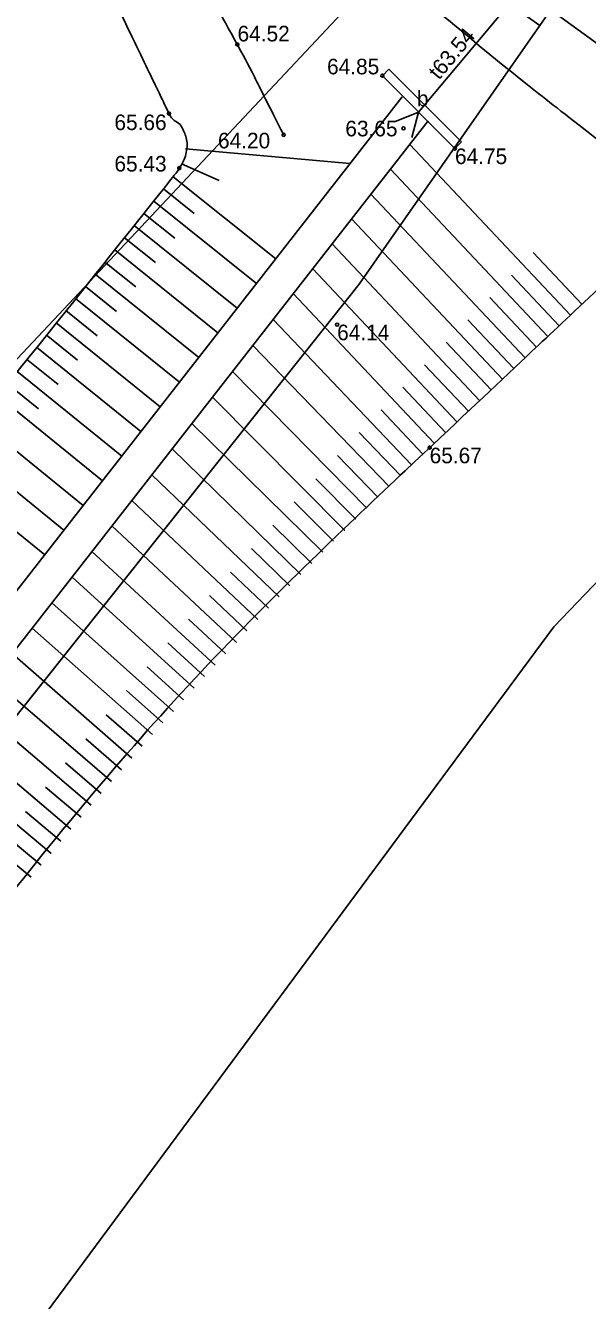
# Model space of a CAD drawing. Extents: x 616607 to 617499, y 408385 to 409695.
# Drawn here: x 617315.69 to 617333.71, y 409488.71 to 409529.59 of the extents above; entities that cross this region are included whole.
import ezdxf

# ---------------------------------------------------------------- set-up
doc = ezdxf.new("R2010")
doc.units = 0
for name, color, linetype in [('BUVE_BDET_####_####_#', 7, 'Continuous'), ('BUVE_BDET_####_TKST_#', 7, 'Continuous'), ('CELI_CMAL_####_####_#', 7, 'Continuous'), ('HIDG_GRAV_####_####_#', 7, 'Continuous'), ('HIDT_CAUR_####_####_#', 7, 'Continuous'), ('HIDT_CAUR_####_TKST_#', 7, 'Continuous'), ('HIDT_ELEM_####_####_#', 7, 'Continuous'), ('RAMI_UZMR_####_####_#', 7, 'Continuous'), ('RELJ_AATZ_####_TKST_#', 7, 'Continuous'), ('RELJ_ELEM_####_####_#', 7, 'Continuous'), ('RELJ_NOGA_####_####_#', 7, 'Continuous'), ('RELJ_NOGL_####_####_#', 7, 'Continuous'), ('ROBZ_PROJ_####_####_#', 7, 'Continuous'), ('ROBZ_UZMR_####_####_#', 7, 'Continuous')]:
    doc.layers.add(name, color=color, linetype=linetype)

# ---------------------------------------------------------------- blocks, each defined once
blk = doc.blocks.new('PKT')
at = {"layer": 'RELJ_ELEM_####_####_#'}
blk.add_circle((0, 0), 0.05, dxfattribs=at)
blk = doc.blocks.new('CAURT')
at = {"layer": 'HIDT_ELEM_####_####_#'}
blk.add_lwpolyline([(0.75, -0.374), (0, 0), (0.75, 0.376)], dxfattribs=at)

msp = doc.modelspace()

# ---------------------------------------------------------------- linework, layer by layer
at = {"layer": 'BUVE_BDET_####_####_#'}
for p, q in [((617327.134, 409527.979), (617327.346, 409528.191)), ((617327.346, 409528.191), (617329.675, 409525.858)), ((617329.463, 409525.646), (617329.675, 409525.858))]:
    msp.add_line(p, q, dxfattribs=at)
msp.add_lwpolyline([(617327.134, 409527.979), (617329.463, 409525.646)], dxfattribs=at)
at = {"layer": 'CELI_CMAL_####_####_#'}
msp.add_lwpolyline([(617323.58, 409536.589), (617338.621, 409525.673)], dxfattribs=at)
at = {"layer": 'HIDG_GRAV_####_####_#'}
for points in [[(617196.049, 409072.553), (617193.886, 409072.979), (617195.921, 409087.874), (617195.921, 409087.874), (617199.518, 409112.516), (617194.569, 409134.842), (617162.019, 409207.474), (617151.93, 409229.107), (617149.428, 409241.28), (617152.359, 409253.938), (617188.564, 409303.055), (617197.968, 409312.659), (617223.456, 409346.169), (617232.567, 409363.51), (617247.671, 409422.509), (617276.576, 409461.456), (617285.007, 409472.526), (617327.765, 409527.3)], [(617198.671, 409072.074), (617200.929, 409072.435), (617202.532, 409075.622), (617201.237, 409087.874), (617202.422, 409112.516), (617197.415, 409136.544), (617162.613, 409207.758), (617153.021, 409229.447), (617150.525, 409241.262), (617153.298, 409253.658), (617189.431, 409302.264), (617198.754, 409312.12), (617224.478, 409345.652), (617234.105, 409363.027), (617250.009, 409421.44), (617285.914, 409471.848), (617328.6, 409526.531)]]:
    msp.add_lwpolyline(points, dxfattribs=at)
at = {"layer": 'HIDT_CAUR_####_####_#'}
msp.add_lwpolyline([(617328.298, 409526.812), (617339.023, 409539.598)], dxfattribs=at)
at = {"layer": 'RAMI_UZMR_####_####_#'}
msp.add_lwpolyline([(617101.571, 408748.246), (617213.472, 409074.039), (617215.883, 409140.56), (617165.121, 409241.478), (617252.137, 409353.424), (617269.572, 409425.099), (617332.631, 409510.312), (617439.945, 409622.037), (617425.373, 409635.959), (617242.079, 409440.82), (617216.614, 409355.716), (617136.613, 409246.751), (617191.828, 409115.62), (617145.545, 408952.8)], dxfattribs=at)
at = {"layer": 'RELJ_NOGA_####_####_#'}
for p, q in [((617319.127, 409529.185), (617319.128, 409529.186)), ((617319.127, 409529.185), (617319.127, 409529.185)), ((617319.344, 409528.735), (617319.344, 409528.735)), ((617319.344, 409528.735), (617319.345, 409528.735)), ((617319.561, 409528.284), (617319.56, 409528.284)), ((617319.561, 409528.284), (617319.562, 409528.285)), ((617319.778, 409527.834), (617319.778, 409527.834)), ((617319.778, 409527.834), (617319.779, 409527.834)), ((617319.995, 409527.383), (617319.994, 409527.383)), ((617319.995, 409527.383), (617319.996, 409527.384)), ((617320.212, 409526.933), (617320.212, 409526.933)), ((617320.212, 409526.933), (617320.213, 409526.933)), ((617320.497, 409526.53), (617320.496, 409526.529)), ((617320.497, 409526.53), (617320.498, 409526.53)), ((617320.783, 409526.132), (617320.783, 409526.132)), ((617320.783, 409526.132), (617320.784, 409526.132)), ((617320.824, 409525.636), (617320.823, 409525.637)), ((617320.824, 409525.636), (617326.095, 409525.161)), ((617333.166, 409520.307), (617328.013, 409525.778)), ((617320.698, 409525.155), (617320.698, 409525.155)), ((617320.698, 409525.155), (617321.901, 409524.624)), ((617320.425, 409524.737), (617320.425, 409524.738)), ((617320.425, 409524.737), (617323.714, 409522.111)), ((617332.438, 409519.621), (617327.39, 409524.981)), ((617320.113, 409524.347), (617320.113, 409524.347)), ((617320.113, 409524.347), (617321.101, 409523.558)), ((617319.801, 409523.956), (617319.8, 409523.957)), ((617319.801, 409523.956), (617323.096, 409521.319)), ((617331.71, 409518.936), (617326.768, 409524.183)), ((617319.489, 409523.566), (617319.489, 409523.566)), ((617319.489, 409523.566), (617320.479, 409522.774)), ((617319.176, 409523.175), (617319.176, 409523.176)), ((617319.176, 409523.175), (617322.481, 409520.531)), ((617330.982, 409518.25), (617326.145, 409523.386)), ((617318.864, 409522.785), (617318.863, 409522.786)), ((617318.864, 409522.785), (617319.856, 409521.99)), ((617318.551, 409522.395), (617318.55, 409522.396)), ((617318.551, 409522.395), (617321.861, 409519.738)), ((617330.254, 409517.564), (617325.523, 409522.588)), ((617333.53, 409520.65), (617331.968, 409522.308)), ((617318.238, 409522.005), (617318.238, 409522.006)), ((617318.238, 409522.005), (617319.233, 409521.207)), ((617317.925, 409521.616), (617317.924, 409521.616)), ((617317.925, 409521.616), (617321.244, 409518.946)), ((617329.527, 409516.879), (617324.9, 409521.791)), ((617332.802, 409519.964), (617331.272, 409521.589)), ((617317.611, 409521.226), (617317.611, 409521.226)), ((617317.611, 409521.226), (617318.609, 409520.424)), ((617317.298, 409520.836), (617317.297, 409520.837)), ((617317.298, 409520.836), (617320.626, 409518.155)), ((617328.799, 409516.193), (617324.277, 409520.993)), ((617332.074, 409519.278), (617330.576, 409520.869)), ((617333.53, 409520.65), (617333.53, 409520.649)), ((617316.984, 409520.447), (617316.984, 409520.447)), ((617316.984, 409520.447), (617317.984, 409519.641)), ((617333.166, 409520.307), (617333.167, 409520.306)), ((617316.67, 409520.058), (617316.67, 409520.058)), ((617316.67, 409520.058), (617320.009, 409517.365)), ((617328.072, 409515.505), (617323.629, 409520.162)), ((617331.346, 409518.593), (617329.879, 409520.15)), ((617332.802, 409519.964), (617332.802, 409519.964)), ((617316.356, 409519.669), (617316.356, 409519.669)), ((617316.356, 409519.669), (617317.359, 409518.859)), ((617330.618, 409517.907), (617329.183, 409519.431)), ((617332.438, 409519.621), (617332.439, 409519.62)), ((617316.042, 409519.28), (617316.041, 409519.28)), ((617316.042, 409519.28), (617319.392, 409516.574)), ((617327.352, 409514.812), (617322.976, 409519.326)), ((617332.074, 409519.278), (617332.075, 409519.278)), ((617315.728, 409518.891), (617315.728, 409518.891)), ((617315.728, 409518.891), (617316.734, 409518.077)), ((617329.891, 409517.221), (617328.487, 409518.712)), ((617331.71, 409518.936), (617331.711, 409518.935)), ((617315.414, 409518.502), (617318.775, 409515.784)), ((617326.636, 409514.114), (617322.329, 409518.497)), ((617330.982, 409518.25), (617330.983, 409518.249)), ((617331.346, 409518.593), (617331.347, 409518.593)), ((617315.099, 409518.113), (617316.109, 409517.295)), ((617329.163, 409516.536), (617327.79, 409517.993)), ((617330.618, 409517.907), (617330.619, 409517.907)), ((617314.784, 409517.725), (617318.157, 409514.993)), ((617325.925, 409513.41), (617321.684, 409517.67)), ((617330.254, 409517.564), (617330.255, 409517.564)), ((617328.435, 409515.85), (617327.091, 409517.269)), ((617329.891, 409517.221), (617329.891, 409517.221)), ((617314.155, 409516.948), (617317.54, 409514.201)), ((617325.22, 409512.701), (617321.03, 409516.833)), ((617329.527, 409516.879), (617329.527, 409516.878)), ((617313.525, 409516.171), (617316.924, 409513.413)), ((617327.711, 409515.16), (617326.389, 409516.535)), ((617328.799, 409516.193), (617328.799, 409516.192)), ((617329.163, 409516.536), (617329.163, 409516.536)), ((617324.52, 409511.987), (617320.39, 409516.013)), ((617326.993, 409514.464), (617325.691, 409515.798)), ((617328.435, 409515.85), (617328.435, 409515.85)), ((617312.894, 409515.395), (617316.306, 409512.621)), ((617328.072, 409515.505), (617328.073, 409515.505)), ((617323.825, 409511.268), (617319.742, 409515.183)), ((617326.28, 409513.763), (617324.998, 409515.059)), ((617327.711, 409515.16), (617327.711, 409515.16)), ((617327.352, 409514.812), (617327.352, 409514.812)), ((617323.136, 409510.544), (617319.097, 409514.356)), ((617325.572, 409513.056), (617324.306, 409514.313)), ((617326.636, 409514.114), (617326.637, 409514.113)), ((617326.993, 409514.464), (617326.993, 409514.464)), ((617326.28, 409513.763), (617326.28, 409513.763)), ((617322.451, 409509.815), (617318.462, 409513.544)), ((617324.87, 409512.345), (617323.622, 409513.568)), ((617325.925, 409513.41), (617325.926, 409513.41)), ((617325.572, 409513.056), (617325.572, 409513.056)), ((617321.771, 409509.082), (617317.821, 409512.723)), ((617324.172, 409511.628), (617322.939, 409512.817)), ((617325.22, 409512.701), (617325.221, 409512.701)), ((617323.48, 409510.906), (617322.263, 409512.067)), ((617324.87, 409512.345), (617324.87, 409512.345)), ((617321.097, 409508.343), (617317.183, 409511.904)), ((617324.52, 409511.987), (617324.521, 409511.986)), ((617322.793, 409510.18), (617321.589, 409511.311)), ((617323.825, 409511.268), (617323.826, 409511.267)), ((617324.172, 409511.628), (617324.172, 409511.628)), ((617320.427, 409507.601), (617316.54, 409511.081)), ((617323.48, 409510.906), (617323.48, 409510.906)), ((617322.111, 409509.449), (617320.919, 409510.553)), ((617323.136, 409510.544), (617323.136, 409510.543)), ((617319.762, 409506.854), (617315.905, 409510.268)), ((617322.793, 409510.18), (617322.793, 409510.18)), ((617321.433, 409508.713), (617320.253, 409509.792)), ((617322.451, 409509.815), (617322.452, 409509.814)), ((617319.102, 409506.103), (617315.267, 409509.45)), ((617322.111, 409509.449), (617322.111, 409509.449)), ((617320.761, 409507.973), (617319.591, 409509.028)), ((617321.771, 409509.082), (617321.772, 409509.081)), ((617318.446, 409505.348), (617314.628, 409508.632)), ((617321.433, 409508.713), (617321.434, 409508.713)), ((617320.094, 409507.228), (617318.933, 409508.263)), ((617321.097, 409508.343), (617321.097, 409508.343)), ((617317.796, 409504.588), (617313.994, 409507.819)), ((617320.427, 409507.601), (617320.428, 409507.6)), ((617320.761, 409507.973), (617320.761, 409507.972)), ((617319.431, 409506.479), (617318.277, 409507.493)), ((617320.094, 409507.228), (617320.094, 409507.228)), ((617317.15, 409503.825), (617313.361, 409507.009)), ((617319.762, 409506.854), (617319.763, 409506.853)), ((617318.773, 409505.726), (617317.626, 409506.721)), ((617319.431, 409506.479), (617319.431, 409506.479)), ((617316.508, 409503.058), (617312.73, 409506.201)), ((617318.12, 409504.968), (617316.977, 409505.945)), ((617319.102, 409506.103), (617319.102, 409506.102)), ((617318.773, 409505.726), (617318.774, 409505.726)), ((617315.871, 409502.287), (617312.094, 409505.385)), ((617317.472, 409504.207), (617316.334, 409505.169)), ((617318.446, 409505.348), (617318.447, 409505.347)), ((617318.12, 409504.968), (617318.121, 409504.968)), ((617316.828, 409503.442), (617315.693, 409504.391)), ((617317.796, 409504.588), (617317.796, 409504.588)), ((617317.472, 409504.207), (617317.472, 409504.207)), ((617316.189, 409502.673), (617315.057, 409503.61)), ((617317.15, 409503.825), (617317.15, 409503.824)), ((617316.828, 409503.442), (617316.828, 409503.442)), ((617316.189, 409502.673), (617316.189, 409502.673)), ((617316.508, 409503.058), (617316.509, 409503.057)), ((617315.871, 409502.287), (617315.872, 409502.286))]:
    msp.add_line(p, q, dxfattribs=at)
for points in [[(617323.43, 409534.875), (617325.254, 409533.269), (617327.041, 409531.618), (617328.903, 409530.056), (617331.485, 409527.887), (617334.171, 409525.842), (617336.806, 409523.735)], [(617148.095, 409250.281), (617149.367, 409254.282), (617150.639, 409258.284), (617151.912, 409262.285), (617156.597, 409277.022), (617171.021, 409286.603), (617180.379, 409298.915), (617194.802, 409317.89), (617212.921, 409334.355), (617223.034, 409356.295), (617225.913, 409362.541), (617226.817, 409369.327), (617228.782, 409375.821), (617233.86, 409392.605), (617237.843, 409409.628), (617244.376, 409426.063), (617252.258, 409445.895), (617268.673, 409460.708), (617281.86, 409477.296), (617294.583, 409493.301), (617307.725, 409508.821), (617320.496, 409524.825), (617320.543, 409524.885), (617320.584, 409524.948), (617320.623, 409525.013), (617320.843, 409525.374), (617320.906, 409525.909), (617320.728, 409526.275), (617320.636, 409526.463), (617320.388, 409526.567), (617320.294, 409526.764), (617319.61, 409528.184), (617318.926, 409529.604), (617318.242, 409531.024)], [(617336.806, 409523.735), (617334.087, 409521.174), (617331.368, 409518.613), (617328.65, 409516.053), (617321.193, 409509.03), (617314.57, 409501.094), (617308.568, 409492.793), (617305.546, 409488.614), (617302.537, 409484.426), (617299.516, 409480.247), (617296.49, 409476.063), (617293.469, 409471.875), (617290.436, 409467.695), (617287.772, 409464.025), (617284.965, 409460.461), (617282.252, 409456.826), (617279.55, 409453.205), (617276.887, 409449.558), (617274.256, 409445.882), (617271.624, 409442.206), (617269.17, 409438.414), (617266.782, 409434.573), (617265.581, 409432.642), (617264.455, 409430.674), (617263.346, 409428.69), (617262.228, 409426.69), (617261.169, 409424.668), (617260.166, 409422.606), (617258.56, 409419.302), (617257.132, 409415.931), (617255.903, 409412.47), (617254.682, 409409.035), (617253.531, 409405.585), (617252.579, 409402.073), (617251.627, 409398.563), (617250.683, 409395.052), (617249.746, 409391.538), (617248.81, 409388.023), (617247.876, 409384.508), (617246.956, 409380.989), (617246.456, 409379.078), (617246.028, 409377.149), (617245.649, 409375.21), (617245.269, 409373.268), (617244.984, 409371.31), (617244.622, 409369.366), (617244.259, 409367.42), (617243.878, 409365.48), (617243.456, 409363.545), (617243.245, 409362.576), (617242.967, 409361.625), (617242.691, 409360.672), (617242.413, 409359.713), (617242.093, 409358.772), (617241.734, 409357.838), (617241.092, 409356.173), (617240.315, 409354.578), (617239.389, 409353.048), (617238.465, 409351.519), (617237.498, 409350.034), (617236.402, 409348.636), (617235.3, 409347.23), (617234.195, 409345.828), (617233.083, 409344.431), (617231.973, 409343.038), (617230.863, 409341.647), (617229.743, 409340.262), (617227.764, 409337.815), (617225.693, 409335.438), (617223.461, 409333.217), (617221.215, 409330.983), (617218.873, 409328.856), (617216.607, 409326.646), (617214.346, 409324.442), (617212.093, 409322.231), (617209.875, 409319.98), (617208.771, 409318.86), (617207.791, 409317.635), (617206.772, 409316.432), (617205.753, 409315.229), (617204.825, 409314.017), (617203.96, 409312.646), (617203.768, 409312.342), (617203.633, 409312.004), (617203.62, 409311.655), (617203.607, 409311.284), (617203.603, 409310.913), (617203.599, 409310.542), (617203.595, 409310.167), (617203.603, 409309.793), (617203.596, 409309.419), (617203.588, 409309.066), (617203.48, 409308.714), (617203.309, 409308.4), (617202.615, 409307.13), (617201.9, 409305.914), (617201.16, 409304.689), (617200.419, 409303.462), (617199.689, 409302.232), (617198.921, 409301.021), (617197.385, 409298.6), (617195.744, 409296.251), (617194.012, 409293.966), (617188.331, 409286.47), (617182.548, 409279.072), (617176.617, 409271.78), (617175.091, 409269.904), (617173.565, 409268.03), (617172.006, 409266.181), (617170.46, 409264.348), (617168.875, 409262.548), (617167.326, 409260.717), (617165.749, 409258.854), (617164.19, 409256.978), (617162.652, 409255.082), (617161.86, 409254.106), (617161.109, 409253.1), (617160.341, 409252.105), (617159.552, 409251.081), (617158.796, 409250.055), (617158.061, 409248.97), (617157.091, 409247.54), (617156.549, 409245.874), (617156.301, 409244.175), (617156.178, 409243.327), (617156.153, 409242.478), (617156.175, 409241.631), (617156.198, 409240.798), (617156.24, 409239.966), (617156.347, 409239.134), (617156.709, 409236.311), (617157.141, 409233.481), (617158.294, 409230.866), (617161.329, 409223.986), (617164.552, 409217.339), (617167.894, 409210.677), (617170.758, 409204.966), (617173.578, 409199.236), (617176.506, 409193.56), (617179.423, 409187.907), (617182.384, 409182.277), (617185.301, 409176.624), (617188.243, 409170.922), (617191.171, 409165.213), (617194.071, 409159.489), (617195.541, 409156.585), (617196.952, 409153.652), (617198.382, 409150.727), (617199.832, 409147.761), (617201.227, 409144.774), (617202.61, 409141.772), (617203.681, 409139.449), (617204.533, 409137.047), (617205.282, 409134.589), (617206.022, 409132.164), (617206.554, 409129.71), (617206.943, 409127.212), (617207.329, 409124.726), (617207.611, 409122.242), (617207.809, 409119.738), (617208.005, 409117.248), (617208.126, 409114.753), (617208.097, 409112.263), (617208.074, 409110.266), (617207.983, 409108.256), (617207.635, 409106.282), (617207.283, 409104.281), (617206.913, 409102.294), (617206.558, 409100.3), (617206.203, 409098.306), (617205.85, 409096.331), (617205.506, 409094.315), (617205.165, 409092.324), (617205.06, 409090.322), (617205.116, 409088.325), (617205.171, 409086.355), (617205.316, 409084.384), (617205.484, 409082.414), (617205.653, 409080.435), (617205.914, 409078.469), (617206.09, 409076.495), (617206.126, 409076.085), (617206.005, 409075.66), (617206.103, 409075.26)]]:
    msp.add_open_spline(points, degree=3, dxfattribs=at)
at = {"layer": 'RELJ_NOGL_####_####_#'}
msp.add_open_spline([(617320.178, 409532.963), (617320.946, 409531.637), (617321.747, 409530.328), (617322.481, 409528.983), (617323.001, 409528.03), (617323.474, 409527.05), (617323.97, 409526.084)], degree=3, dxfattribs=at)
at = {"layer": 'ROBZ_PROJ_####_####_#'}
msp.add_lwpolyline([(617318.399, 409542.625), (617324.935, 409534.695), (617332.188, 409529.592), (617326.39, 409521.291), (617255.789, 409432.426), (617250.98, 409414.497), (617224.174, 409428.057)], dxfattribs=at)
at = {"layer": 'ROBZ_UZMR_####_####_#'}
msp.add_lwpolyline([(617232.583, 409073.745), (617196.025, 409075.262), (617200.886, 409119.423), (617196.507, 409136.07), (617150.138, 409230.13), (617148.652, 409247.272), (617201.229, 409318.934), (617233.453, 409357.938), (617244.928, 409391.934), (617250.98, 409414.497), (617255.789, 409432.426), (617326.39, 409521.291), (617332.188, 409529.592), (617332.358, 409529.835), (617335.391, 409534.333), (617341.051, 409533.641), (617349.913, 409536.856), (617370.73, 409556.7), (617378.749, 409547.935), (617381.343, 409545.1)], dxfattribs=at)

# ---------------------------------------------------------------- block references
at = {"layer": 'HIDT_ELEM_####_####_#', "rotation": -132.04161365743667}
msp.add_blockref('CAURT', (617328.298, 409526.812), dxfattribs=at)
at = {"layer": 'RELJ_ELEM_####_####_#'}
for p in [(617322.481, 409528.983), (617327.134, 409527.979), (617320.294, 409526.764), (617323.97, 409526.084), (617327.812, 409526.291), (617329.463, 409525.646), (617320.623, 409525.013), (617325.685, 409519.998), (617328.65, 409516.053)]:
    msp.add_blockref('PKT', p, dxfattribs=at)

# ---------------------------------------------------------------- texts
at = {"layer": 'BUVE_BDET_####_TKST_#'}
msp.add_text('b', height=0.5, dxfattribs=at).set_placement((617328.241, 409526.996))
at = {"layer": 'HIDT_CAUR_####_TKST_#'}
msp.add_text('t63.54', height=0.5, rotation=50.0102, dxfattribs=at).set_placement((617328.949, 409527.821))
at = {"layer": 'RELJ_AATZ_####_TKST_#'}
for s, p in [('64.52', (617322.491, 409529.079)), ('64.85', (617325.361, 409528.023)), ('65.66', (617318.543, 409526.235)), ('63.65', (617325.947, 409526.035)), ('64.20', (617321.864, 409525.65)), ('64.75', (617329.463, 409525.146)), ('65.43', (617318.543, 409524.908)), ('64.14', (617325.685, 409519.498)), ('65.67', (617328.65, 409515.553))]:
    msp.add_text(s, height=0.5, dxfattribs=at).set_placement(p)

doc.saveas('drawing.dxf')
